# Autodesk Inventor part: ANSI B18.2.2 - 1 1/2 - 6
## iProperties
Author: Elise Moss
Created: 2002-02
Part Number: ANSI B18.2.2 - 1 1/2 - 6
Catalog Web Link: file:///C:/Program%20Files/Autodesk/Inventor%205/Content/Ansi/index.htm?doNavigateId=DE078585-AA5B-49AF-80AC-F4CB93B11BE8|6C222486D7E211D4BA8200C04F798F98|true
Description: Hex Flat Nut
Document SubType Name: Standard Catalog Part
Standard: ANSI B18.2.2 - 1 1/2 - 6
Designer: Elise Moss
CLASSIFICATION: 31161727 un/spsc
MANUFACTURER: ANSI Standard System
Control State: 0
Master: False
Checked Out: False
PropertySet Name: Design Tracking Control
Shininess: 64.0
Angle Display Precision: 2
Document Length Units: 11269
Document Angle Units: 11283
Document Time Units: 11279
Document Mass Units: 11290
Document Length Units Precision: 3
Document Angle Units Precision: 2
Compacted: True
PropertySet Name: _Private Model Information
Density: 0.0
Volumn: 0.0
Area: 0.0
PropertySet Name: Model Information
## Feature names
1. Base1
